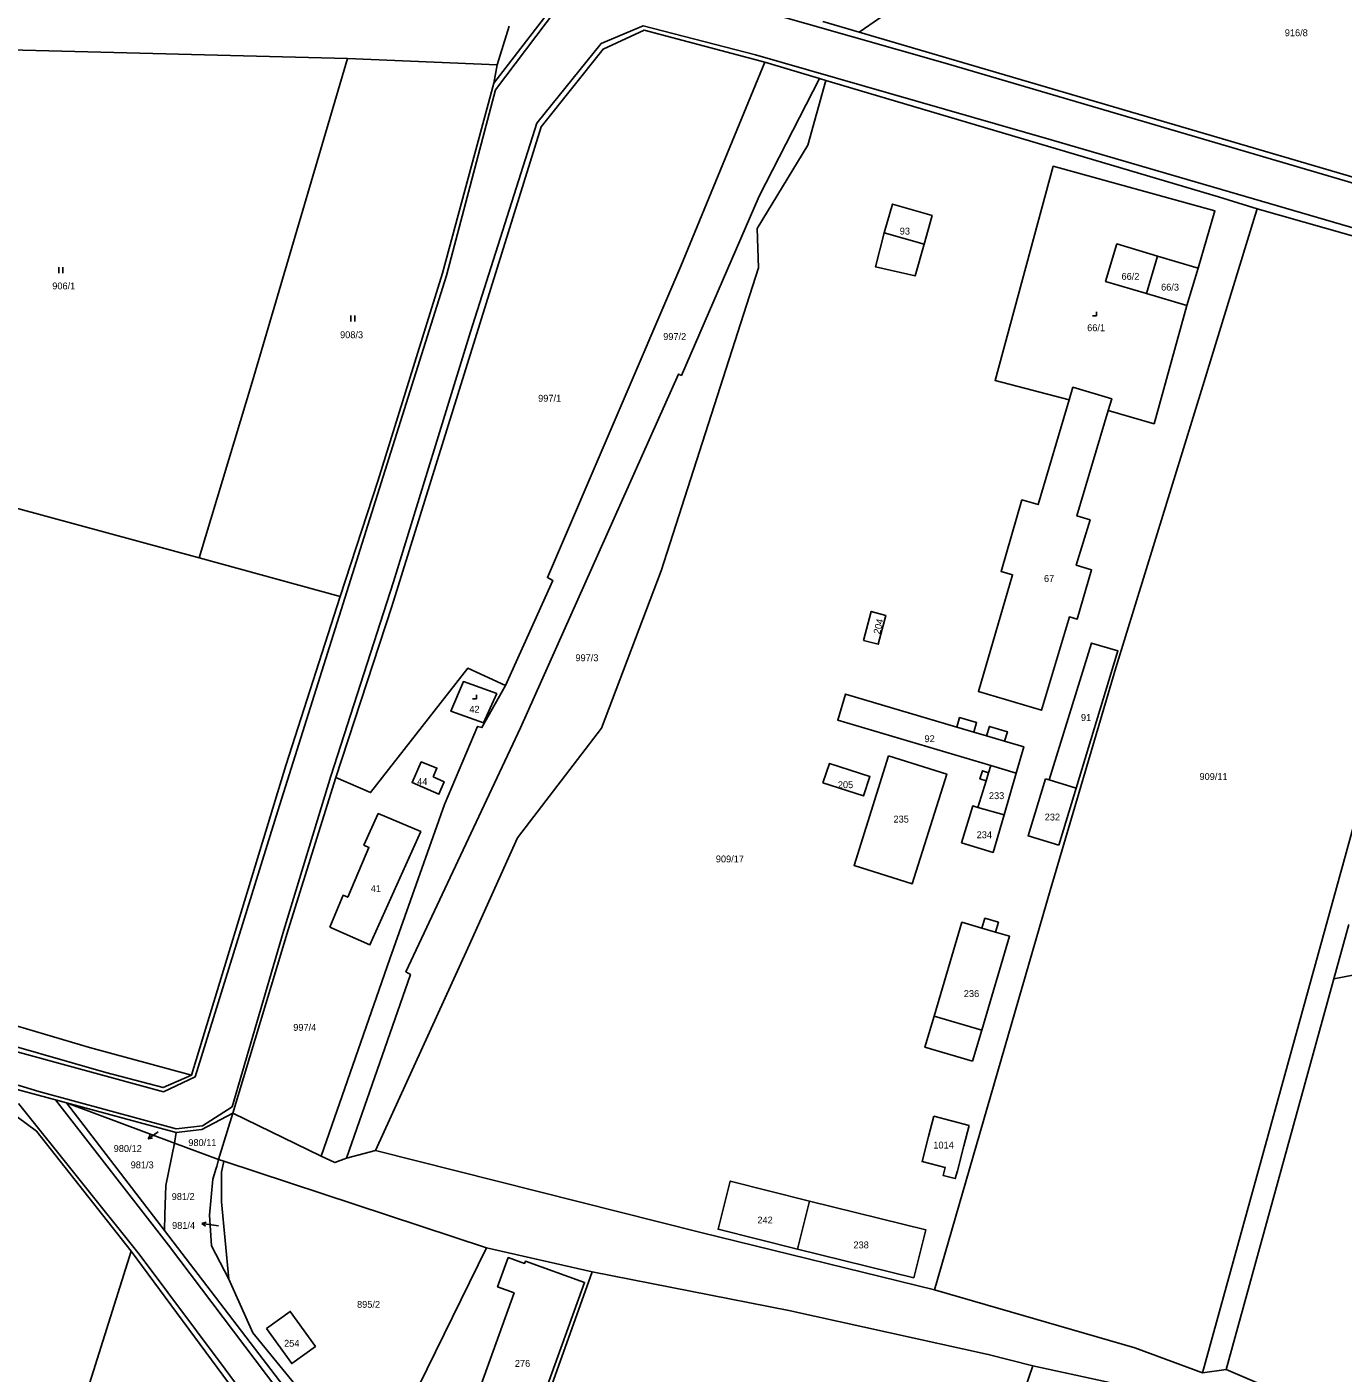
# Model space of a CAD drawing. Extents: x -7476540 to -746055, y -11317203 to -1129777.
# Drawn here: x -750733.8 to -750408.5, y -1131564.4 to -1131231.7 of the extents above; entities that cross this region are included whole.
import ezdxf

# ---------------------------------------------------------------- set-up
doc = ezdxf.new("R2010")
doc.units = 0
for name, color, linetype in [('Hranice parcel', 7, 'Continuous'), ('Parcelní čísla', 7, 'Continuous'), ('Pop  PČ popisy', 7, 'Continuous'), ('Vnitřní kresba', 7, 'Continuous'), ('Značky kultur', 7, 'Continuous')]:
    doc.layers.add(name, color=color, linetype=linetype)

msp = doc.modelspace()

# ---------------------------------------------------------------- linework, layer by layer
at = {"layer": 'Hranice parcel'}
for p, q in [((-750528.14, -1131233.04), (-750537.12, -1131230.36)), ((-750617.63, -1131241.09), (-750614.64, -1131231.58)), ((-750528.14, -1131233.04), (-750360.45, -1131282.22)), ((-750654.61, -1131239.55), (-750762.57, -1131236.72)), ((-750617.63, -1131241.09), (-750654.61, -1131239.55)), ((-750618.46, -1131245.66), (-750617.63, -1131241.09)), ((-750551.42, -1131240.45), (-750537.93, -1131244.49)), ((-750537.93, -1131244.49), (-750536.32, -1131244.96)), ((-750368.77, -1131294.03), (-750429.73, -1131276.7)), ((-750457.13, -1131297.58), (-750454.39, -1131288.36)), ((-750454.39, -1131288.36), (-750444.35, -1131291.34)), ((-750447.09, -1131300.56), (-750444.35, -1131291.34)), ((-750447.09, -1131300.56), (-750457.13, -1131297.58)), ((-750736.77, -1131350.61), (-750691.26, -1131362.92)), ((-750656.43, -1131372.51), (-750691.26, -1131362.92)), ((-750495.6, -1131414.26), (-750496.15, -1131416.05)), ((-750495.6, -1131414.26), (-750489.3, -1131416.18)), ((-750492.25, -1131426.5), (-750489.3, -1131416.18)), ((-750481.12, -1131417.84), (-750482.08, -1131417.55)), ((-750481.12, -1131417.84), (-750474.47, -1131419.87)), ((-750478.76, -1131433.97), (-750474.47, -1131419.87)), ((-750498.76, -1131424.62), (-750492.25, -1131426.5)), ((-750410.8, -1131466.96), (-750407.11, -1131453.55)), ((-750437.4, -1131563.54), (-750410.8, -1131466.96)), ((-750699.83, -1131529.24), (-750724.05, -1131497.67)), ((-750724.05, -1131497.67), (-750696.92, -1131504.94)), ((-750724.05, -1131497.67), (-750697.37, -1131507.59)), ((-750682.9, -1131500.24), (-750686.52, -1131511.63)), ((-750661.14, -1131510.79), (-750682.9, -1131500.24)), ((-750509.65, -1131500.94), (-750500.91, -1131503.23)), ((-750696.92, -1131504.94), (-750697.37, -1131507.59)), ((-750686.52, -1131511.63), (-750697.37, -1131507.59)), ((-750647.66, -1131509.4), (-750654.85, -1131511.29)), ((-750686.52, -1131511.63), (-750685.18, -1131512.07)), ((-750620.21, -1131533.45), (-750685.18, -1131512.07)), ((-750543.37, -1131533.85), (-750540.36, -1131521.95)), ((-750650.01, -1131594.16), (-750699.83, -1131529.24)), ((-750620.21, -1131533.45), (-750648.35, -1131590.75)), ((-750594.09, -1131539.43), (-750620.21, -1131533.45)), ((-750543.37, -1131533.85), (-750514.57, -1131540.88)), ((-750708.07, -1131534.34), (-750682.59, -1131568.73)), ((-750624.91, -1131625.6), (-750594.09, -1131539.43)), ((-750443.23, -1131564.35), (-750437.4, -1131563.54))]:
    msp.add_line(p, q, dxfattribs=at)
for points in [[(-750485.93, -1131208.1), (-750494.34, -1131210.1), (-750520.95, -1131228.16), (-750523.07, -1131229.6), (-750528.14, -1131233.04)], [(-750582.93, -1131218.86), (-750600.91, -1131222.79), (-750618.46, -1131245.66)], [(-750657.5, -1131417.24), (-750643.67, -1131374.99), (-750606.75, -1131256.44), (-750591.42, -1131237.23), (-750581.25, -1131232.5), (-750551.42, -1131240.45)], [(-750691.26, -1131362.92), (-750678.15, -1131319.54), (-750654.61, -1131239.55)], [(-750615.54, -1131394.52), (-750603.88, -1131368.52), (-750605.19, -1131367.81), (-750572.16, -1131290.88), (-750551.42, -1131240.45)], [(-750654.85, -1131511.29), (-750639.05, -1131465.94), (-750640.14, -1131465.25), (-750611.8, -1131404.98), (-750572.81, -1131317.54), (-750572.05, -1131317.87), (-750552.87, -1131273.55), (-750537.93, -1131244.49)], [(-750656.43, -1131372.51), (-750647.07, -1131344), (-750631.13, -1131292.58), (-750618.46, -1131245.66)], [(-750536.32, -1131244.96), (-750540.79, -1131260.97), (-750553.31, -1131281.58), (-750552.98, -1131291.26), (-750577.1, -1131366.16), (-750591.83, -1131405.06), (-750612.55, -1131432.12), (-750624.87, -1131459.41), (-750647.66, -1131509.4)], [(-750429.73, -1131276.7), (-750439.28, -1131273.7), (-750536.32, -1131244.96)], [(-750444.35, -1131291.34), (-750440.19, -1131277.15), (-750480.13, -1131266.16), (-750494.54, -1131319.09), (-750476.19, -1131323.87)], [(-750521.91, -1131282.62), (-750524.12, -1131291.01), (-750514.29, -1131293.25), (-750512.06, -1131285.43), (-750510.1, -1131278.35), (-750519.89, -1131275.52), (-750521.91, -1131282.62)], [(-750429.73, -1131276.7), (-750430.27, -1131278.28), (-750443.16, -1131320.42), (-750464.65, -1131390.12), (-750480.94, -1131445.17), (-750509.47, -1131543.89)], [(-750457.13, -1131297.58), (-750467.2, -1131294.62), (-750464.42, -1131285.37), (-750454.39, -1131288.36)], [(-750443.23, -1131564.35), (-750407.78, -1131435.86), (-750368.77, -1131294.03)], [(-750466.58, -1131326.57), (-750455.23, -1131329.82), (-750447.09, -1131300.56)], [(-750476.19, -1131323.87), (-750475.27, -1131320.78), (-750465.7, -1131323.62), (-750466.58, -1131326.57)], [(-750476.19, -1131323.87), (-750483.89, -1131349.8), (-750487.87, -1131348.63), (-750493.03, -1131366.3), (-750490.18, -1131367.14), (-750498.65, -1131395.95), (-750483.01, -1131400.62), (-750476.15, -1131377.55), (-750474.21, -1131378.09), (-750470.67, -1131365.89), (-750474.44, -1131364.78), (-750471.04, -1131353.57), (-750474.3, -1131352.58), (-750466.58, -1131326.57)], [(-750693.19, -1131490.82), (-750669.82, -1131414.31), (-750656.43, -1131372.51)], [(-750527.03, -1131383.35), (-750523.4, -1131384.29), (-750521.53, -1131377.16), (-750525.15, -1131376.2), (-750527.03, -1131383.35)], [(-750474.47, -1131419.87), (-750464.15, -1131385.97), (-750470.69, -1131384.02), (-750481.12, -1131417.84)], [(-750657.5, -1131417.24), (-750648.89, -1131420.96), (-750624.83, -1131390.2), (-750615.54, -1131394.52)], [(-750617.72, -1131396.46), (-750625.94, -1131393.53), (-750629.03, -1131400.86), (-750620.99, -1131403.76), (-750617.72, -1131396.46)], [(-750615.54, -1131394.52), (-750621.35, -1131404.91), (-750622.47, -1131404.61), (-750630.58, -1131423.94), (-750644.12, -1131462.03), (-750661.14, -1131510.79)], [(-750489.3, -1131416.18), (-750487.43, -1131409.66), (-750492.18, -1131408.27), (-750491.49, -1131405.93), (-750495.94, -1131404.62), (-750496.62, -1131406.95), (-750499.78, -1131406.02), (-750499.08, -1131403.65), (-750503.29, -1131402.43), (-750503.99, -1131404.78), (-750531.53, -1131396.61), (-750533.41, -1131403.04), (-750495.6, -1131414.26)], [(-750633.43, -1131417.07), (-750632.48, -1131414.92), (-750636.37, -1131413.39), (-750638.62, -1131418.49), (-750632.01, -1131421.36), (-750630.7, -1131418.27), (-750633.43, -1131417.07)], [(-750537.07, -1131418.55), (-750527.01, -1131421.78), (-750525.46, -1131416.97), (-750535.45, -1131413.74), (-750537.07, -1131418.55)], [(-750520.86, -1131411.87), (-750529.37, -1131439), (-750515.01, -1131443.51), (-750506.48, -1131416.39), (-750520.86, -1131411.87)], [(-750682.9, -1131500.24), (-750669.3, -1131454.92), (-750657.5, -1131417.24)], [(-750496.15, -1131416.05), (-750497.64, -1131415.58), (-750498.27, -1131417.56), (-750496.75, -1131418.03), (-750498.76, -1131424.62)], [(-750482.08, -1131417.55), (-750486.38, -1131431.67), (-750478.76, -1131433.97)], [(-750498.76, -1131424.62), (-750500.05, -1131424.25), (-750502.79, -1131433.36)], [(-750658.95, -1131454.2), (-750649.06, -1131458.62), (-750636.5, -1131430.59), (-750646.98, -1131426.16), (-750650.54, -1131433.94), (-750649.31, -1131434.53), (-750654.54, -1131446.82), (-750655.66, -1131446.34), (-750658.95, -1131454.2)], [(-750502.79, -1131433.36), (-750495.03, -1131435.75), (-750492.25, -1131426.5)], [(-750494.41, -1131455.47), (-750493.69, -1131453.03), (-750497.05, -1131452.03), (-750497.77, -1131454.48), (-750502.74, -1131453.01), (-750509.59, -1131476.24), (-750511.85, -1131483.92), (-750500.07, -1131487.35)], [(-750812.53, -1131455.02), (-750740.7, -1131477.39), (-750718.37, -1131483.96), (-750693.19, -1131490.82)], [(-750500.07, -1131487.35), (-750497.81, -1131479.71), (-750490.94, -1131456.49), (-750494.41, -1131455.47)], [(-750693.19, -1131490.82), (-750700.17, -1131493.87), (-750714.32, -1131490.16), (-750747.12, -1131480.73), (-750773.74, -1131472.31), (-750807.97, -1131461.22)], [(-750067.88, -1131564.53), (-750249.66, -1131511.44), (-750403.56, -1131465.6), (-750410.8, -1131466.96)], [(-750744.87, -1131492.04), (-750726.78, -1131496.93), (-750724.05, -1131497.67)], [(-750745.91, -1131495.61), (-750738.46, -1131499.46), (-750731.45, -1131504.65), (-750708.07, -1131534.34)], [(-750696.92, -1131504.94), (-750690.64, -1131504.23), (-750682.9, -1131500.24)], [(-750500.91, -1131503.23), (-750502.23, -1131508.27), (-750503.85, -1131514.43), (-750504.35, -1131516.37), (-750507.37, -1131515.58), (-750506.86, -1131513.65), (-750512.55, -1131512.15), (-750510.95, -1131505.97), (-750509.65, -1131500.94)], [(-750697.37, -1131507.59), (-750699.52, -1131518.06), (-750699.78, -1131525.23), (-750699.83, -1131529.24)], [(-750654.85, -1131511.29), (-750657.75, -1131512.43), (-750661.14, -1131510.79)], [(-750647.66, -1131509.4), (-750567.28, -1131529.67), (-750509.47, -1131543.89)], [(-750683.93, -1131541.21), (-750688.25, -1131533.02), (-750688.69, -1131525.4), (-750687.9, -1131516.49), (-750687.04, -1131513.78), (-750686.9, -1131513.35), (-750686.52, -1131511.63)], [(-750685.18, -1131512.07), (-750685.72, -1131514.75), (-750685.77, -1131522.08), (-750683.93, -1131541.21)], [(-750540.36, -1131521.95), (-750560, -1131517), (-750563, -1131528.9), (-750543.37, -1131533.85)], [(-750514.57, -1131540.88), (-750511.65, -1131529.03), (-750540.36, -1131521.95)], [(-750763.62, -1131706.58), (-750750.64, -1131667.2), (-750727.2, -1131595.02), (-750708.07, -1131534.34)], [(-750626, -1131579.6), (-750611.41, -1131584.85), (-750596.01, -1131542.05), (-750610.61, -1131536.79), (-750610.81, -1131537.34), (-750614.87, -1131535.9), (-750617.49, -1131543.16), (-750613.43, -1131544.62), (-750626, -1131579.6)], [(-750485.16, -1131562.68), (-750496.23, -1131559.81), (-750545.47, -1131549), (-750594.09, -1131539.43)], [(-750683.93, -1131541.21), (-750678.02, -1131554.46), (-750648.35, -1131590.75)], [(-750509.47, -1131543.89), (-750459.97, -1131558.18), (-750443.23, -1131564.35)], [(-750674.63, -1131553.43), (-750668.38, -1131562.08), (-750662.51, -1131557.84), (-750668.76, -1131549.19), (-750674.63, -1131553.43)], [(-750536.84, -1131710.51), (-750503.54, -1131616.08), (-750485.16, -1131562.68)], [(-750485.16, -1131562.68), (-750466.95, -1131566.61), (-750458.62, -1131568.48), (-750444.15, -1131573.19), (-750412.62, -1131586.23), (-750409.9, -1131587.47)], [(-750260.97, -1131651.42), (-750263.94, -1131648.99), (-750292.29, -1131625.83), (-750369.3, -1131592.74), (-750437.4, -1131563.54)]]:
    msp.add_lwpolyline(points, dxfattribs=at)
at = {"layer": 'Pop  PČ popisy'}
for p, q in [((-750701.41, -1131504.81), (-750703.87, -1131506.53)), ((-750703.87, -1131506.53), (-750703.33, -1131505.55)), ((-750703.87, -1131506.53), (-750702.76, -1131506.37)), ((-750690.61, -1131527.46), (-750689.55, -1131527.11)), ((-750687.64, -1131527.88), (-750690.61, -1131527.46)), ((-750690.61, -1131527.46), (-750689.69, -1131528.1)), ((-750686.46, -1131528.03), (-750687.64, -1131527.88))]:
    msp.add_line(p, q, dxfattribs=at)
at = {"layer": 'Vnitřní kresba'}
for p, q in [((-750600.48, -1131224.07), (-750617.99, -1131247.26)), ((-750506.88, -1131240.71), (-750566.04, -1131223.81)), ((-750581.51, -1131231.45), (-750591.91, -1131235.86)), ((-750553.71, -1131238.62), (-750581.51, -1131231.45)), ((-750591.91, -1131235.86), (-750607.82, -1131255.55)), ((-750480.64, -1131259.63), (-750553.71, -1131238.62)), ((-750344.21, -1131288.58), (-750506.88, -1131240.71)), ((-750617.99, -1131247.26), (-750630.11, -1131293.16)), ((-750607.82, -1131255.55), (-750624.2, -1131307.05)), ((-750379.57, -1131289.16), (-750480.64, -1131259.63)), ((-750512.06, -1131285.43), (-750521.91, -1131282.62)), ((-750630.11, -1131293.16), (-750671.83, -1131425.44)), ((-750624.2, -1131307.05), (-750643.23, -1131368.86)), ((-750643.23, -1131368.86), (-750658.75, -1131416.88)), ((-750503.99, -1131404.78), (-750499.78, -1131406.02)), ((-750496.62, -1131406.95), (-750492.18, -1131408.27)), ((-750658.75, -1131416.88), (-750670.34, -1131454.96)), ((-750496.15, -1131416.05), (-750496.75, -1131418.03)), ((-750671.83, -1131425.44), (-750692.23, -1131491.25)), ((-750670.34, -1131454.96), (-750683.13, -1131498.67)), ((-750494.41, -1131455.47), (-750497.77, -1131454.48)), ((-750509.59, -1131476.24), (-750497.81, -1131479.71)), ((-750730.88, -1131494.84), (-750767.75, -1131483.73)), ((-750700.09, -1131494.96), (-750739.31, -1131484.25)), ((-750692.23, -1131491.25), (-750700.09, -1131494.96)), ((-750696.97, -1131504.08), (-750730.88, -1131494.84)), ((-750726.78, -1131496.93), (-750698.84, -1131532.83)), ((-750735.89, -1131497.78), (-750706.11, -1131535.06)), ((-750683.13, -1131498.67), (-750690.46, -1131503.32)), ((-750690.46, -1131503.32), (-750696.97, -1131504.08)), ((-750698.84, -1131532.83), (-750651.39, -1131595.59)), ((-750706.11, -1131535.06), (-750684.86, -1131563.5)), ((-750684.86, -1131563.5), (-750660.16, -1131596.47))]:
    msp.add_line(p, q, dxfattribs=at)
at = {"layer": 'Značky kultur'}
for p, q in [((-750725.93, -1131292.63), (-750725.93, -1131291.13)), ((-750724.93, -1131292.63), (-750724.93, -1131291.13)), ((-750653.8, -1131304.52), (-750653.8, -1131303.02)), ((-750652.8, -1131304.52), (-750652.8, -1131303.02)), ((-750470.48, -1131303.14), (-750469.48, -1131303.14)), ((-750469.48, -1131303.14), (-750469.48, -1131302.14)), ((-750623.71, -1131397.78), (-750622.71, -1131397.78)), ((-750622.71, -1131397.78), (-750622.71, -1131396.78))]:
    msp.add_line(p, q, dxfattribs=at)

# ---------------------------------------------------------------- texts
at = {"layer": 'Parcelní čísla'}
for s, p in [('916/8', (-750422.91, -1131234.02)), ('93', (-750518.09, -1131283.04)), ('66/2', (-750463.27, -1131294.23)), ('906/1', (-750727.57, -1131296.6)), ('66/3', (-750453.49, -1131296.89)), ('908/3', (-750656.43, -1131308.66)), ('997/2', (-750576.56, -1131309.1)), ('66/1', (-750471.76, -1131306.93)), ('997/1', (-750607.47, -1131324.36)), ('67', (-750482.44, -1131368.91)), ('997/3', (-750598.25, -1131388.5)), ('42', (-750624.48, -1131401.23)), ('91', (-750473.3, -1131403.26)), ('92', (-750511.96, -1131408.5)), ('44', (-750637.38, -1131419.1)), ('909/11', (-750444, -1131417.85)), ('205', (-750533.39, -1131419.87)), ('233', (-750496.05, -1131422.58)), ('235', (-750519.63, -1131428.38)), ('232', (-750482.25, -1131427.86)), ('234', (-750499.07, -1131432.25)), ('909/17', (-750563.55, -1131438.22)), ('41', (-750648.84, -1131445.55)), ('236', (-750502.25, -1131471.5)), ('997/4', (-750668, -1131479.85)), ('980/11', (-750693.94, -1131508.32)), ('1014', (-750509.79, -1131508.94)), ('980/12', (-750712.39, -1131509.79)), ('981/3', (-750708.19, -1131513.83)), ('981/2', (-750698.05, -1131521.66)), ('981/4', (-750697.96, -1131528.8)), ('242', (-750553.27, -1131527.47)), ('238', (-750529.53, -1131533.62)), ('895/2', (-750652.23, -1131548.31)), ('254', (-750670.27, -1131557.93)), ('276', (-750613.23, -1131562.9))]:
    msp.add_text(s, height=1.7, dxfattribs=at).set_placement(p)
msp.add_text('204', height=1.7, rotation=77, dxfattribs=at).set_placement((-750522.97, -1131381.94))

doc.saveas('drawing.dxf')
